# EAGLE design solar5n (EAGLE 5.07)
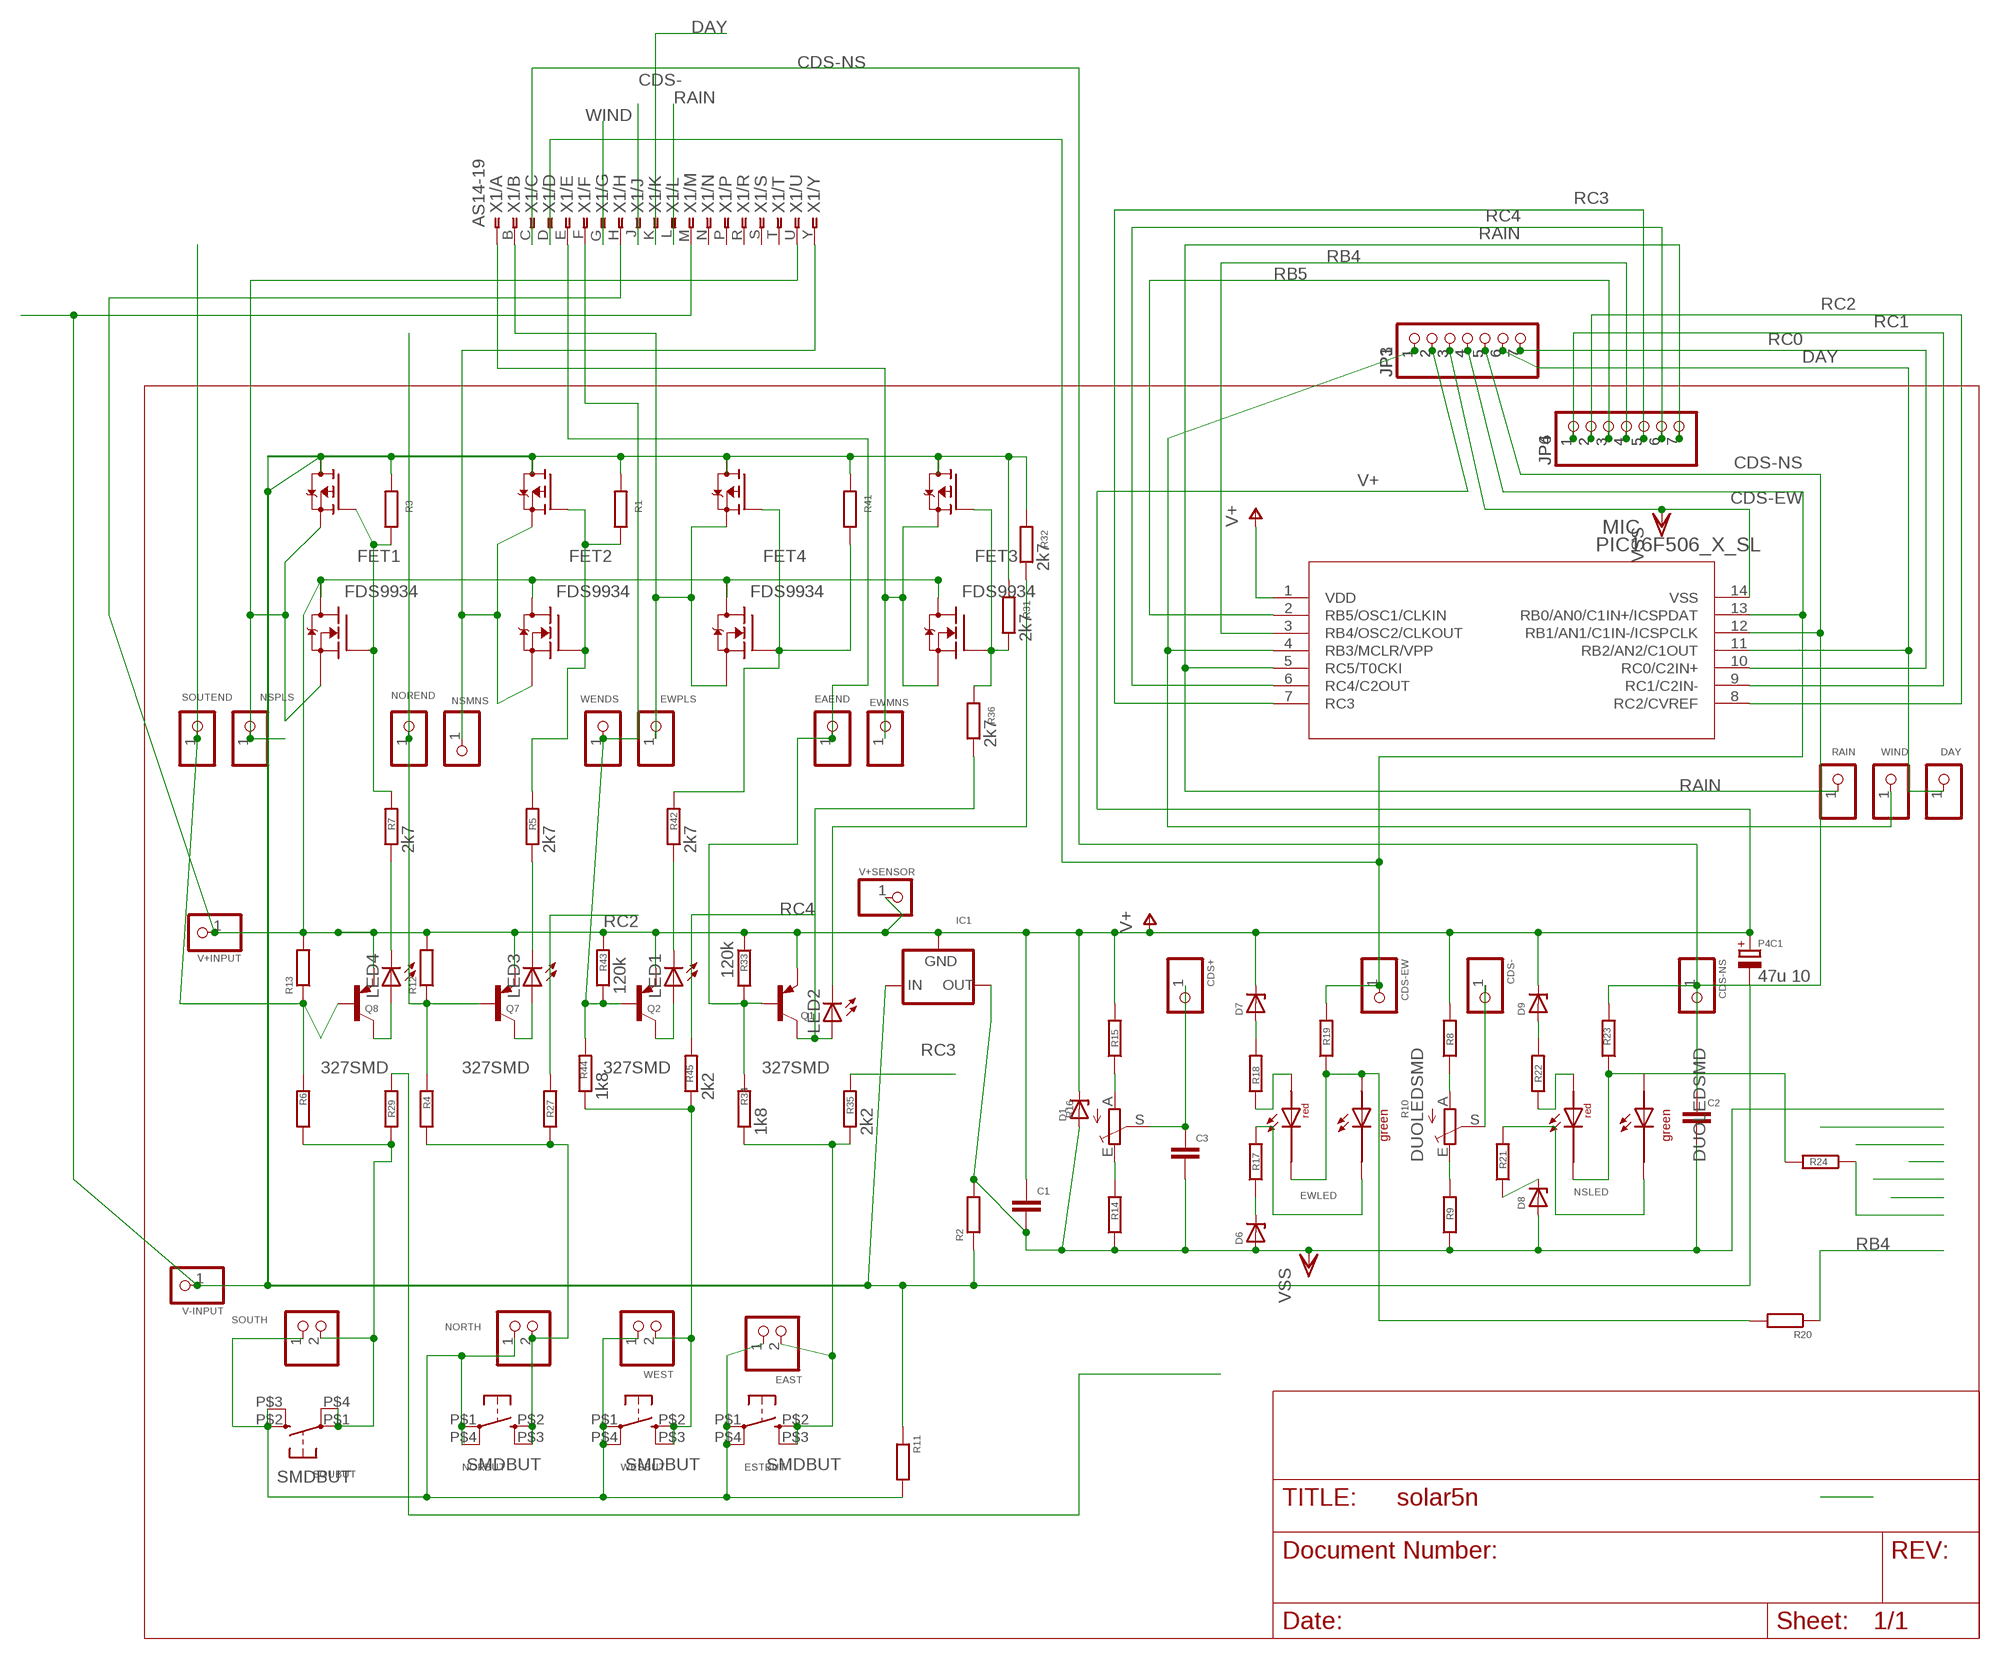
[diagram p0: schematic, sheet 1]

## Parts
C1  C-EUC1206  [C1206]
C2  C-EUC1206  [C1206]
C3  C-EUC1206  [C1206]
CDS+  PINHD-1X1INCH  [1X01]
CDS-  PINHD-1X1INCH  [1X01]
CDS-EW  PINHD-1X1INCH  [1X01]
CDS-NS  PINHD-1X1INCH  [1X01]
D1  ZENER-DIODESOD80C  [SOD80C]
D6  ZENER-DIODESOD80C  [SOD80C]
D7  ZENER-DIODESOD80C  [SOD80C]
D8  ZENER-DIODESOD80C  [SOD80C]
D9  ZENER-DIODESOD80C  [SOD80C]
DAY  PINHD-1X1INCH  [1X01]
EAEND  PINHD-1X1INCH  [1X01]
EAST  PINHD-1X2STR  [1X02]
ESTBUT  SMDBUT  [SMD10/5]
EWLED  DUOLEDSMD  [DUOLEDSMD]
EWMNS  PINHD-1X10MM6  [1X01M]
EWPLS  PINHD-1X10MM6  [1X01M]
FET1  FDS9934  [SO-8]
FET2  FDS9934  [SO-8]
FET3  FDS9934  [SO-8]
FET4  FDS9934  [SO-8]
IC1  79LXX  [79LXX]
JP1  PINHD-1X7  [1X07]
JP3  PINHD-1X7  [1X07]
JP4  PINHD-1X7  [1X07]
JP6  PINHD-1X7  [1X07]
LED1  LEDCHIPLED_1206  [CHIPLED_1206]
LED2  LEDCHIPLED_1206  [CHIPLED_1206]
LED3  LEDCHIPLED_1206  [CHIPLED_1206]
LED4  LEDCHIPLED_1206  [CHIPLED_1206]
MIC  PIC16F506_X_SL  [SOIC14_N_MC]
NORBUT  SMDBUT  [SMD10/5]
NOREND  PINHD-1X1INCH  [1X01]
NORTH  PINHD-1X2STR  [1X02]
NSLED  DUOLEDSMD  [DUOLEDSMD]
NSMNS  PINHD-1X1INCH  [1X01]
NSPLS  PINHD-1X10MM6  [1X01M]
P4C1  47u 10  CPOL-EUE5-8.5  [E5-8,5]
Q1  327SMD  BC327SMD  [SOT23-BEC]
Q2  327SMD  BC327SMD  [SOT23-BEC]
Q7  327SMD  BC327SMD  [SOT23-BEC]
Q8  327SMD  BC327SMD  [SOT23-BEC]
R1  R-EU_R0805  [R0805]
R2  R-EU_R0805  [R0805]
R3  R-EU_R0805  [R0805]
R4  R-EU_R1206  [R1206]
R5  2k7  R-EU_R0805  [R0805]
R6  R-EU_R1206  [R1206]
R7  2k7  R-EU_R0805  [R0805]
R8  R-EU_R1206  [R1206]
R9  R-EU_R0805  [R0805]
R10  TRIM_EU-CA6V  [CA6V]
R11  R-EU_R0805  [R0805]
R12  R-EU_R1206  [R1206]
R13  R-EU_R0805  [R0805]
R14  R-EU_R1206  [R1206]
R15  R-EU_R1206  [R1206]
R16  TRIM_EU-CA6V  [CA6V]
R17  R-EU_R1206  [R1206]
R18  R-EU_R1206  [R1206]
R19  R-EU_R0805  [R0805]
R20  R-EU_R0805  [R0805]
R21  R-EU_R1206  [R1206]
R22  R-EU_R1206  [R1206]
R23  R-EU_R0805  [R0805]
R24  R-EU_R0805  [R0805]
R27  R-EU_R0805  [R0805]
R29  R-EU_R0805  [R0805]
R31  2k7  R-EU_R0805  [R0805]
R32  2k7  R-EU_R0805  [R0805]
R33  120k  R-EU_R0805  [R0805]
R34  1k8  R-EU_R0805  [R0805]
R35  2k2  R-EU_R0805  [R0805]
R36  2k7  R-EU_R0805  [R0805]
R41  R-EU_R0805  [R0805]
R42  2k7  R-EU_R0805  [R0805]
R43  120k  R-EU_R0805  [R0805]
R44  1k8  R-EU_R0805  [R0805]
R45  2k2  R-EU_R0805  [R0805]
RAIN  PINHD-1X1INCH  [1X01]
SOUBUT  SMDBUT  [SMD10/5]
SOUTEND  PINHD-1X1INCH  [1X01]
SOUTH  PINHD-1X2STR  [1X02]
V+INPUT  PINHD-1X1INCH  [1X01]
V+SENSOR  PINHD-1X10MM6  [1X01M]
V-INPUT  PINHD-1X10MM6  [1X01M]
WENDS  PINHD-1X1INCH  [1X01]
WESBUT  SMDBUT  [SMD10/5]
WEST  PINHD-1X2STR  [1X02]
WIND  PINHD-1X1INCH  [1X01]
X1  AS14-19  AS14-19OLIVE  [Y28M-19TK]

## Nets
CDS-: CDS-.1 R10.S X1.J
CDS-EW: CDS-EW.1 JP1.4 JP3.4 MIC.13(RB0/AN0/C1IN+/ICSPDAT) R19.2 X1.D
CDS-NS: C2.1 CDS-NS.1 JP1.5 JP3.5 MIC.12(RB1/AN1/C1IN-/ICSPCLK) R23.2 X1.C
DAY: DAY.1 JP1.6 JP3.6 MIC.11(RB2/AN2/C1OUT) X1.K
MOTO1: EWPLS.1 FET4.1(Q1S) FET4.3(Q2S) X1.B
MOTOR1: FET1.1(Q1S) FET1.3(Q2S) NSPLS.1 X1.U
MOTOR2: FET2.1(Q1S) FET2.3(Q2S) NSMNS.1 X1.Y
MOTOR3: EWMNS.1 FET3.1(Q1S) FET3.3(Q2S) X1.A
N$1: R9.2 R10.E
N$2: LED4.A Q8.C
N$3: LED3.A Q7.C
N$4: FET2.2(Q1G) FET2.4(Q2G) R1.1 R5.2
N$5: LED4.C R7.1
N$6: EWLED.AGRN EWLED.CRED R19.1 R20.2
N$8: LED3.C R5.1
N$9: R6.1 R29.1 SOUBUT.P$1(P) SOUBUT.P$4(P1) SOUTH.2
N$10: LED1.A Q2.C
N$11: EAST.2 ESTBUT.P$2(S) ESTBUT.P$3(S1) R34.1 R35.1
N$13: R24.1
N$14: D7.A R18.2
N$17: NORBUT.P$2(S) NORBUT.P$3(S1) NORTH.2 R4.1 R27.1
N$18: R8.1 R10.A
N$19: Q8.B R6.2 R13.1 SOUTEND.1
N$20: NOREND.1 Q7.B R4.2 R12.1
N$21: R14.2 R16.E
N$22: R15.1 R16.A
N$23: C3.1 CDS+.1 R16.S
N$25: EWLED.ARED R18.1
N$27: D6.C R17.1
N$28: EWLED.CGRN R17.2
N$29: EAST.1 ESTBUT.P$1(P) ESTBUT.P$4(P1) NORBUT.P$1(P) NORBUT.P$4(P1) NORTH.1 R11.2 SOUBUT.P$2(S) SOUBUT.P$3(S1) SOUTH.1 WESBUT.P$1(P) WESBUT.P$4(P1) WEST.1
N$30: NSLED.AGRN NSLED.CRED R23.1 R24.2
N$32: Q2.B R43.1 R44.2 WENDS.1 X1.F
N$33: EAEND.1 Q1.B R33.2 R34.2 X1.E
N$37: LED2.A Q1.C R36.1
N$39: R44.1 R45.1 WESBUT.P$2(S) WESBUT.P$3(S1) WEST.2
N$41: D9.A R22.2
N$42: NSLED.ARED R22.1
N$43: D8.C R21.1
N$44: NSLED.CGRN R21.2
N$50: FET1.2(Q1G) FET1.4(Q2G) R3.1 R7.2
N$51: LED1.C R42.1
N$54: FET4.2(Q1G) FET4.4(Q2G) R41.1 R42.2
N$55: FET3.2(Q1G) FET3.4(Q2G) R31.1 R36.2
N$56: LED2.C R32.1
RAIN: JP4.7 JP6.7 MIC.5(RC5/T0CKI) RAIN.1 X1.L
RB4: JP4.4 JP6.4 MIC.3(RB4/OSC2/CLKOUT) R20.1
RB5: JP4.3 JP6.3 MIC.2(RB5/OSC1/CLKIN)
RC0: JP1.7 JP3.7 MIC.10(RC0/C2IN+)
RC1: JP4.1 JP6.1 MIC.9(RC1/C2IN-) R29.2
RC2: JP4.2 JP6.2 MIC.8(RC2/CVREF) R27.2
RC3: JP4.5 JP6.5 MIC.7(RC3) R35.2
RC4: JP4.6 JP6.6 MIC.6(RC4/C2OUT) R45.2
V+: C1.1 D1.C D7.C D9.C FET1.7(Q1D2) FET1.8(Q1D1) FET2.7(Q1D2) FET2.8(Q1D1) FET3.7(Q1D2) FET3.8(Q1D1) FET4.7(Q1D2) FET4.8(Q1D1) IC1.GND JP1.2 JP3.2 MIC.1(VDD) P4C1.+ Q1.E Q2.E Q7.E Q8.E R8.2 R12.2 R13.2 R15.2 R33.1 R43.2 V+INPUT.1 V+SENSOR.1 X1.H
V-: FET1.5(Q2D2) FET1.6(Q2D) FET2.5(Q2D2) FET2.6(Q2D) FET3.5(Q2D2) FET3.6(Q2D) FET4.5(Q2D2) FET4.6(Q2D) IC1.IN P4C1.- R1.2 R2.1 R3.2 R11.1 R31.2 R32.2 R41.2 V-INPUT.1 X1.M
VSS: C1.2 C2.2 C3.2 D1.A D6.A D8.A IC1.OUT JP1.3 JP3.3 MIC.14(VSS) R2.2 R9.1 R14.1
WIND: JP1.1 JP3.1 MIC.4(RB3/MCLR/VPP) WIND.1 X1.G
Unconnected: X1.N X1.P X1.R X1.S X1.T

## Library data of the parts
C1-C3 = rcl-2:C-EU: CAPACITOR, European symbol
CDS+ CDS- CDS-EW CDS-NS DAY EAEND EWMNS EWPLS NOREND NSMNS NSPLS RAIN SOUTEND V+INPUT V+SENSOR V-INPUT WENDS WIND = pinhead(2):PINHD-1X1: PIN HEADER
D1 D6-D9 = diode-1:ZENER-DIODE: Z-Diode
EAST NORTH SOUTH WEST = pinhead:PINHD-1X2: PIN HEADER
ESTBUT NORBUT SOUBUT WESBUT = switch-omron:SMDBUT
EWLED NSLED = led:DUOLEDSMD
FET1-FET4 = transistor-fet:FDS9934
IC1 = v-reg:79LXX: VOLTAGE REGULATOR
JP1 JP3 JP4 JP6 = pinhead:PINHD-1X7: PIN HEADER
LED1-LED4 = led:LED: LED
MIC = pic16f506mc:PIC16F506_X_SL
P4C1 = rcl:CPOL-EU: POLARIZED CAPACITOR, European symbol
Q1 Q2 Q7 Q8 = transistor-pnp:BC327*: PNP Transistror
R1-R9 R11-R15 R17-R24 R27 R29 R31-R36 R41-R45 = rcl-2:R-EU_: RESISTOR, European symbol
R10 R16 = pot:TRIM_EU-: POTENTIOMETER
X1 = con-deutsch:AS14-19: DEUTSCH Connector

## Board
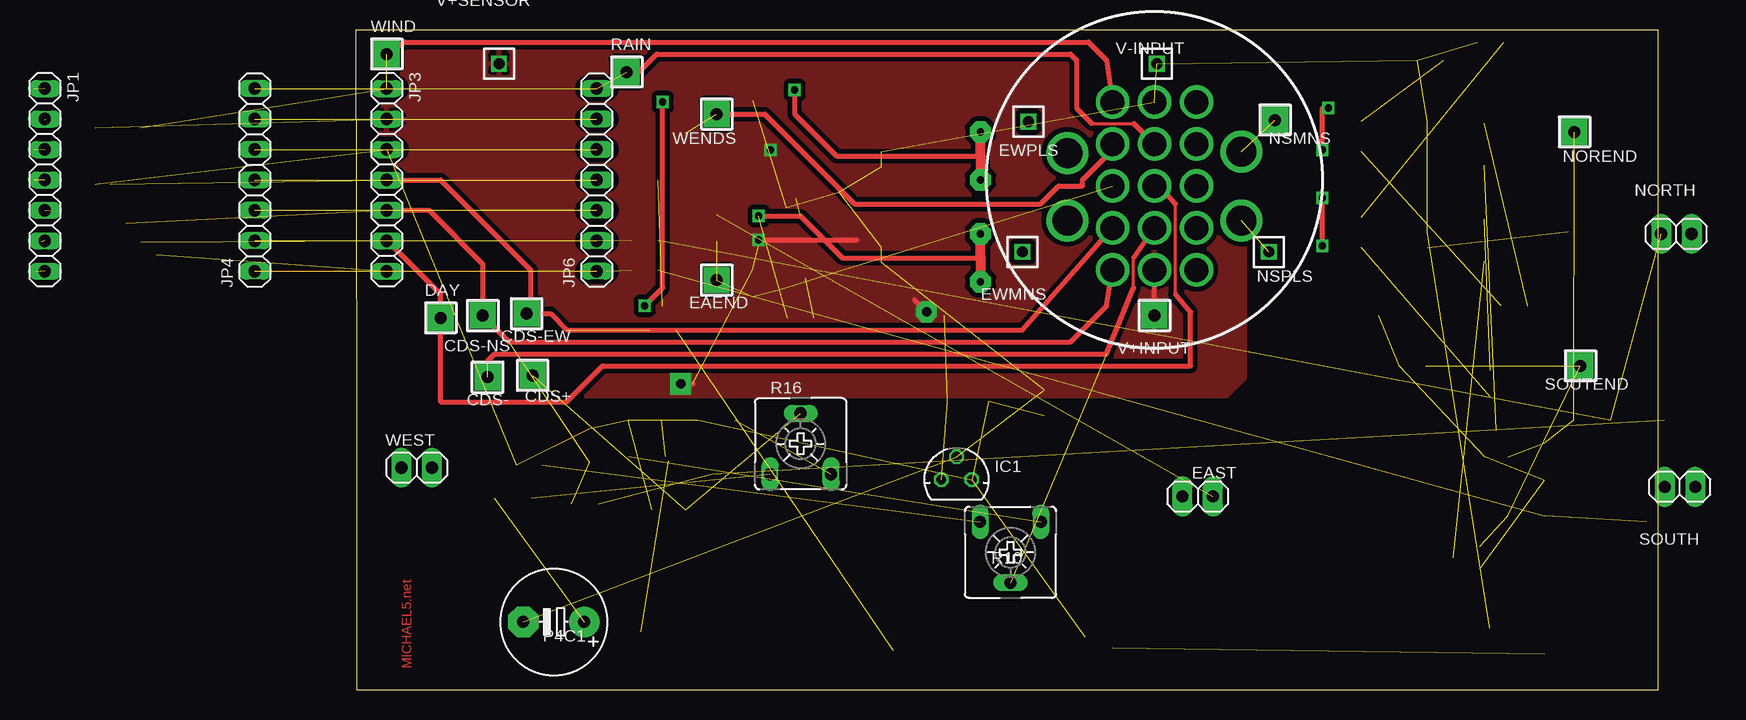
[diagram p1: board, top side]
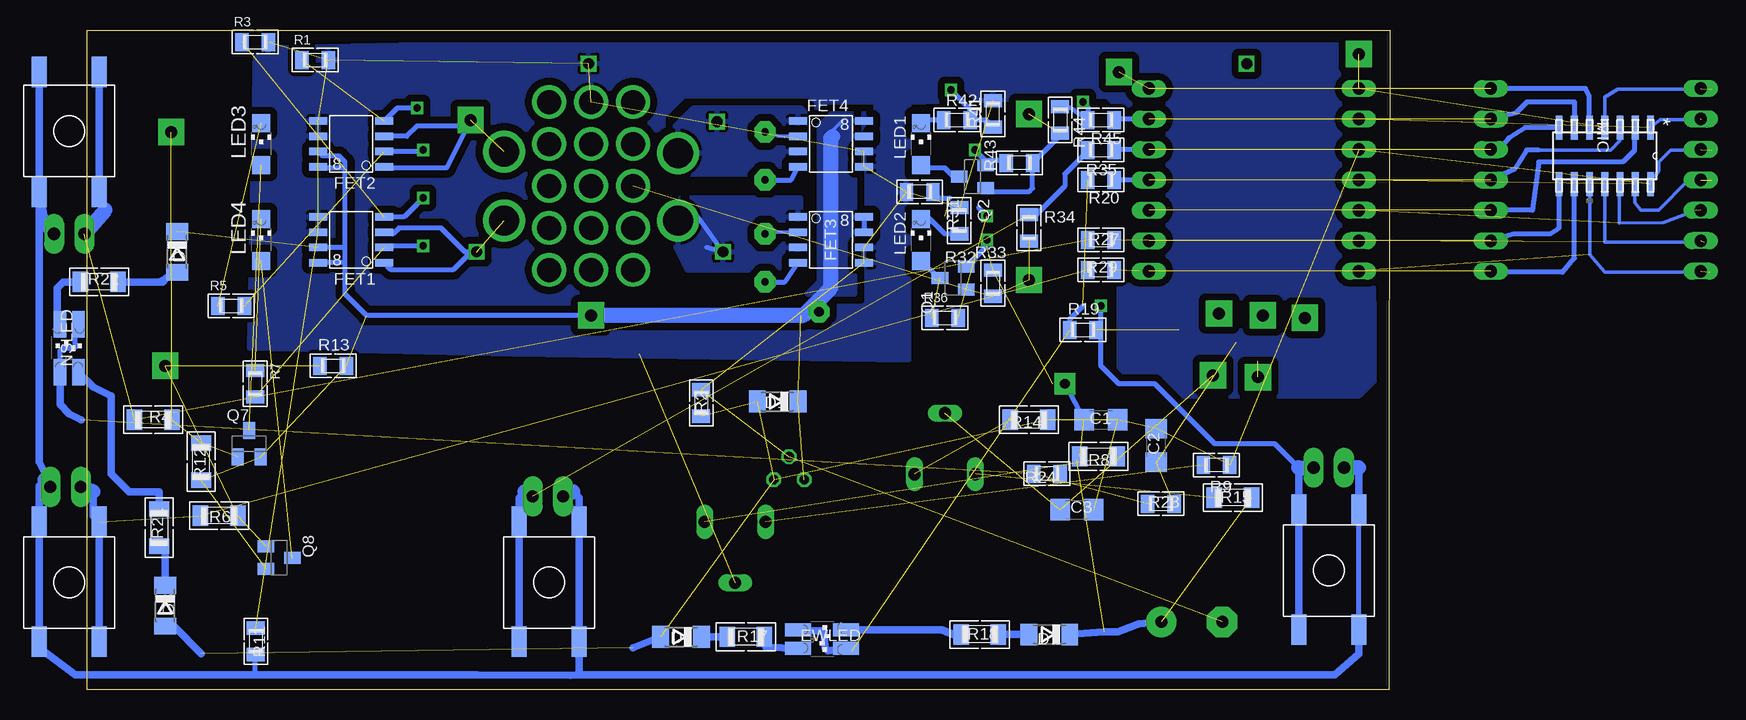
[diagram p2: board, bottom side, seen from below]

Size 108.57 x 55 mm. Coordinates in mm from the lower left corner, seen from the top.
Outline: 0.07,0 108.57,0 108.57,55 0,55 0.07,25 0.07,0
Copper layers (1*16): Top 0.035mm / dielectric 1.5mm / Bottom 0.035mm
Design rules "default *": minimum track width 40mil, minimum drill 30mil, track to track 8mil, track to pad 8mil, pad to pad 8mil, via to via 8mil, smd to smd 8mil, copper to edge 40mil, drill to drill 8mil, minimum pad ring 8mil, minimum via ring 8mil, stop-mask expansion 4mil, vias tented up to drill 0mil, thermal gap 10mil

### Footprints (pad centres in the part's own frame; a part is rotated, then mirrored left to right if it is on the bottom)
C1206 = smd 1.6 x 1.8: 1 -1.4,0; 2 1.4,0
1X01 = drill 1 pad 2.184 square: 1 0,0
SOD80C = smd 1.4 x 1.8: A 1.7,0; C -1.7,0
1X02 = drill 1.016 pad 1.676 long: 1 -1.27,0; 2 1.27,0
SMD10/5 = smd 1.27 x 2.54: P$1 -2.5,0; P$2 2.5,0; P$3 2.5,10; P$4 -2.5,10
DUOLEDSMD = smd 1.067 x 2.184: AGRN 0.77,1.95; ARED -0.77,1.95; CGRN 0.77,-2.05; CRED -0.77,-2.05
1X01M = drill 0.914 square: 1 0,0
SO-8 = smd 1.524 x 0.61: 1 -2.743,1.905; 2 -2.743,0.635; 3 -2.743,-0.635; 4 -2.743,-1.905; 5 2.743,-1.905; 6 2.743,-0.635; 7 2.743,0.635; 8 2.743,1.905
79LXX = drill 0.813 octagon: GND -1.27,0; IN 0,1.905; OUT 1.27,0
1X07 = drill 1.016 long: 1 -7.62,0; 2 -5.08,0; 3 -2.54,0; 4 0,0; 5 2.54,0; 6 5.08,0; 7 7.62,0
CHIPLED_1206 = smd 1.5 x 1.5: A 0,-1.75; C 0,1.75
SOIC14_N_MC = smd 1.981 x 0.559: 1 -2.362,3.81; 2 -2.362,2.54; 3 -2.362,1.27; 4 -2.362,0; 5 -2.362,-1.27; 6 -2.362,-2.54; 7 -2.362,-3.81; 8 2.362,-3.81; 9 2.362,-2.54; 10 2.362,-1.27; 11 2.362,0; 12 2.362,1.27; 13 2.362,2.54; 14 2.362,3.81
E5-8,5 = drill 1 pad 2.54 round: + -2.54,0 | drill 1 pad 2.54 octagon: - 2.54,0
SOT23-BEC = smd 1 x 1.4: B -0.95,-1.1; C 0,1.1; E 0.95,-1.1
R0805 = smd 1.1 x 1.5: 1 -1.1,0; 2 1.1,0
R1206 = smd 1.3 x 1.7: 1 -1.55,0; 2 1.55,0
CA6V = drill 1.016 long: A -2.54,-2.54; E 2.54,-2.54; S 0,2.54
Y28M-19TK = drill 2.5 pad 3.5 round: A -7.25,-2.875; B -7.25,2.75; U 7.25,-2.875; Y 7.25,2.875 | drill 2 pad 2.54 round: C -3.5,-7; D -3.5,-3.5; E -3.5,0; F -3.5,3.5; G -3.5,7; H 0,-7; J 0,-3.5; K 0,0; L 0,3.5; M 0,7; N 3.5,-7; P 3.5,-3.5; R 3.5,0; S 3.5,3.5; T 3.5,7

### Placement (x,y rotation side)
C1  24.07,22.5 0 bottom
C2  19.46,20.35 90 bottom
C3  26.07,15 0 bottom
CDS+  14.72,26.2 0 top
CDS-  10.97,26.05 90 top
CDS-EW  14.22,31.35 0 top
CDS-NS  10.57,31.2 90 top
D1  51.02,24.02 180 bottom
D6  59.07,4.4 180 bottom
D7  28.37,4.6 180 bottom
D8  102.07,7 270 bottom
D9  101.07,36.5 270 bottom
DAY  7.07,31 0 top
EAEND  30.07,34.15 90 top
EAST  70.17,16.1 0 top
ESTBUT  70.07,14 180 bottom
EWLED  47.27,4.2 270 bottom
EWMNS  55.57,36.5 90 top
EWPLS  56.07,47.35 90 top
FET1  86.57,37.5 180 bottom
FET2  86.57,45.5 180 bottom
FET3  46.57,37.5 0 bottom
FET4  46.57,45.5 0 bottom
IC1  50.07,17.5 0 top
JP1  not placed on the board
JP3  2.57,42.5 270 top
JP4  -8.43,42.5 90 top  (outside the outline)
JP6  20.07,42.5 90 top
LED1  39.07,45.5 0 bottom
LED2  39.07,37.5 0 bottom
LED3  94.07,45.5 0 bottom
LED4  94.07,37.5 0 bottom
MIC  -17.93,44.5 270 bottom  (outside the outline)
NORBUT  110.07,41.5 0 bottom
NOREND  101.57,46.5 0 top
NORTH  110.07,38 180 top
NSLED  110.07,28.5 0 bottom
NSMNS  76.62,47.5 0 top
NSPLS  76.12,36.5 0 top
P4C1  16.49,5.64 180 top
Q1  36.4,34.31 90 bottom
Q2  34.78,42.77 90 bottom
Q7  95.07,20.5 0 bottom
Q8  92.57,11 270 bottom
R1  89.57,52.5 0 bottom
R2  57.39,23.89 270 bottom
R3  94.57,54 0 bottom
R4  103.07,22.5 0 bottom
R5  96.57,32 0 bottom
R6  97.57,14.5 0 bottom
R7  94.57,25.5 270 bottom
R8  24.28,19.44 180 bottom
R9  14.44,18.71 180 bottom
R10  54.56,11.44 180 top
R11  94.52,4.02 270 bottom
R12  99.07,19 270 bottom
R13  88.07,27 0 bottom
R14  30.07,22.5 180 bottom
R15  13.07,16 0 bottom
R16  37.07,20.5 0 top
R17  53.67,4.4 0 bottom
R18  34.17,4.6 0 bottom
R19  25.57,30 0 bottom
R20  24.07,42.5 180 bottom
R21  102.57,13.5 90 bottom
R22  107.57,34 0 bottom
R23  19.07,15.5 0 bottom
R24  28.57,18 180 bottom
R27  24.07,37.5 0 bottom
R29  24.07,35 0 bottom
R31  39.17,41.5 180 bottom
R32  35.87,39.1 90 bottom
R33  33.07,33.89 270 bottom
R34  30.07,38.5 270 bottom
R35  24.07,45 0 bottom
R36  37.07,31 0 bottom
R41  33.07,48 90 bottom
R42  36.07,47.5 0 bottom
R43  30.86,43.91 180 bottom
R44  27.47,47.5 270 bottom
R45  24.07,47.5 0 bottom
RAIN  22.57,51.5 0 top
SOUBUT  110.07,14 180 bottom
SOUTEND  102.07,27 0 top
SOUTH  110.37,16.9 180 top
V+INPUT  66.57,31.2 90 top
V+SENSOR  11.92,52.2 90 top
V-INPUT  66.77,52.2 90 top
WENDS  30.07,48 90 top
WESBUT  5.07,15 180 bottom
WEST  5.07,18.5 0 top
WIND  2.57,53 0 top
X1  66.57,42 0 top

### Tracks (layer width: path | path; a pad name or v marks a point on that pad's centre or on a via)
CDS-  (2 unrouted)
  Top 0.254: 64.82,33.5 64.82,36
  Top 0.406: 64.82,36 X1.J | 64.82,33.5 62.57,28 11.57,28 10.97,27.4
CDS-EW  (3 unrouted)
  Top 0.406: JP3.4 7.07,42.5 14.57,35 14.57,31.7 CDS-EW.1 16.22,31.35 17.57,30 55.57,30 X1.D
  Bottom 0.305: MIC.13 -20.43,40.6 -20.93,40 -22.43,40 -24.89,42.46 -26.86,42.46
CDS-NS  (4 unrouted)
  Top 0.406: X1.C 62.57,32 59.57,29 12.77,29 CDS-NS.1 10.57,35.5 6.11,39.96 JP3.5
  Bottom 0.305: MIC.12 -19.13,41.31 -19.13,38.9 -22.81,38.92 -25.46,39.92
DAY  (2 unrouted)
  Top 0.254: 68.32,33 68.32,40.5
  Top 0.406: JP3.6 2.99,37 3.07,37 7.07,33 DAY.1 7.07,24 17.57,24 20.57,27 69.57,27 69.57,31.5 68.32,33 | 68.32,40.5 67.07,42 X1.K
  Bottom 0.305: MIC.11 -17.93,37.3 -26.24,37.3
MOTO1
  Bottom 0.406: FET4.1 49.41,47.5
  pour Bottom (isolate 0.61): 49.57,44.5 48.57,48 49.07,48.5 58.07,48.5 59.57,47 59.57,45 58.57,43 50.07,43
MOTOR1  (1 unrouted)
  Bottom 0.406: FET1.3 83.69,38 83.07,38 82.57,38.5 79.07,38.5 77.07,36.5 NSPLS.1 76.57,36.5 78.07,35 83.23,35 FET1.1
MOTOR2  (1 unrouted)
  Bottom 0.406: FET2.1 83.97,43.59 84.07,43.5 78.62,43.5 NSMNS.1 77.12,47 81.07,47 81.93,46.13 FET2.3
MOTOR3
  Bottom 0.406: 56.94,36.87 EWMNS.1 57.66,39.41
  pour Bottom (isolate 0.61): 49.07,41 59.07,41 59.57,39.5 59.57,37 58.57,35 49.57,35 49.07,36.5
N$1  (1 unrouted)
N$2  (1 unrouted)
N$3  (1 unrouted)
N$4  (via drill 0.6)  (2 unrouted)
  Top 0.406: v80.57,45 80.57,48.5 v81.07,48.5
  Bottom 0.406: FET2.2 80.7,44.87 v80.57,45 | v81.07,48.5 82.73,48.5 FET2.4
N$5  (1 unrouted)
N$6  (2 unrouted)
  Bottom 0.406: R19.1 26.67,30.9 25.57,32
  Bottom 0.61: 44.8,3.23 EWLED.AGRN 46.8,3.23 47.07,3.5 47.17,4.9 48.95,4.9 EWLED.CRED
N$8  (1 unrouted)
N$9  (2 unrouted)
  Bottom 0.61: SOUBUT.P$4 SOUBUT.P$1 108.07,14.5 108.07,16.5
  Bottom 1.27: 108.07,16.5 SOUTH.2
N$10
  Bottom 0.406: Q2.C 36.34,42.77 37.07,43.5 38.82,43.5 LED1.A
N$11  (1 unrouted)
  Bottom 0.406: R35.1 25.17,44.9 27.07,43 27.07,42 29.57,39.5 29.97,39.5 R34.1
  Bottom 0.61: ESTBUT.P$3 ESTBUT.P$2 72.57,16 72.07,16.5
  Bottom 1.27: 72.07,16.5 EAST.2
N$14
  Bottom 0.61: D7.A R18.2
N$17  (2 unrouted)
  Bottom 0.61: NORBUT.P$2 NORBUT.P$3 | NORBUT.P$2 107.57,41 | 107.07,40 NORBUT.P$2
  Bottom 1.27: NORTH.2 107.07,40
N$18  (1 unrouted)
N$19  (3 unrouted)
N$20  (3 unrouted)
N$21  (1 unrouted)
N$22  (1 unrouted)
N$23  (2 unrouted)
N$25
  Bottom 0.61: R18.1 35.49,4.42 36.07,4.5 37.35,5 EWLED.ARED
N$27
  Bottom 0.61: R17.1 D6.C
N$28
  Bottom 0.61: EWLED.CGRN 51.98,3.53 R17.2
N$29
  Bottom 0.406: WESBUT.P$4 WESBUT.P$1 | R11.2 94.57,2.6 94.57,1.25
  Bottom 0.61: WESBUT.P$1 2.57,18.5 | 67.57,1.25 ESTBUT.P$4 ESTBUT.P$1 67.57,16 68.07,16.5 | 67.57,1.25 4.57,1.25 2.57,3 WESBUT.P$4 | 67.57,1.25 68.27,1.2 76.07,1.23 79.57,1.25 94.57,1.25 109.57,1.25 112.57,3.5 SOUBUT.P$3 SOUBUT.P$2 112.57,17 112.07,17.5 | SOUTH.1 112.07,18 112.57,19 NORBUT.P$1 | NORBUT.P$1 112.07,39 | NORBUT.P$1 NORBUT.P$4
  Bottom 1.27: 2.57,18.5 WEST.1 | 68.07,16.5 EAST.1 | 112.07,17.5 SOUTH.1 | 112.07,39 NORTH.1
N$30  (2 unrouted)
  Bottom 0.406: NSLED.CRED 110.84,28.23 110.57,28.5 109.57,28.5 109.57,30.18 NSLED.AGRN
  Bottom 0.61: NSLED.CRED 110.84,23.77 110.07,23 109.07,22.5
N$32  (1 unrouted)
  Top 0.406: WENDS.1 34.07,48 41.57,40.5 57.07,40.5 58.57,42 60.57,42 60.57,42.5 63.07,45 X1.F
  Bottom 0.406: R44.2 27.47,46.2 R43.1 29.76,41.81 30.07,41.5 33.35,41.5 Q2.B
N$33  (4 unrouted)
N$37  (1 unrouted)
  Bottom 0.406: Q1.C 37.63,34.31 LED2.A
N$39  (via drill 0.6)
  Top 0.406: v25.57,49 25.57,33.5 v24.07,32
  Bottom 0.406: 7.57,18.5 9.57,20.5 14.57,20.5 19.57,25.5 22.57,25.5 24.07,27 v24.07,32 | R44.1 26.57,48.5 R45.1 25.17,48.6 v25.57,49
  Bottom 0.61: WESBUT.P$3 WESBUT.P$2 7.57,18.5
  Bottom 1.27: 7.57,18.5 WEST.2
N$41
  Bottom 0.61: D9.A 101.97,34.32 | 101.97,34.32 102.57,34 | R22.2 102.29,34 101.97,34.32
N$42
  Bottom 0.61: R22.1 110.57,34 111.07,33.5 111.07,30.68 NSLED.ARED
N$43
  Bottom 0.61: D8.C 102.07,11.58 R21.1
N$44
  Bottom 0.61: R21.2 102.57,16.5 105.07,16.5 106.57,18 106.57,24.5 108.07,25.22 NSLED.CGRN
N$50  (via drill 0.6)  (2 unrouted)
  Top 0.406: v80.57,37 v80.57,41
  Bottom 0.406: FET1.4 82.16,39.41 v80.57,41 | v80.57,37 83.69,37 FET1.2
N$51
  Bottom 0.406: LED1.C 39.07,47.5 R42.1
N$54  (via drill 0.6, 0.6 pad 1.78)
  Top 0.406: v36.57,50 36.57,48 40.07,44.5 52.07,44.5
  Top 0.813: v52.07,42.5 52.07,44.5 v52.07,46.5
  Bottom 0.305: FET4.2 50.94,46.13 v52.07,46.5
  Bottom 0.406: FET4.4 49.91,42.5 v52.07,42.5 | R41.1 33.67,47.5 R42.2 34.97,48.4 v36.57,50
N$55  (via drill 0.6, 0.6 pad 1.78)  (2 unrouted)
  Top 0.406: v33.57,39.5 37.07,39.5 40.57,36 52.07,36
  Top 0.813: v52.07,34 52.07,36 v52.07,38
  Bottom 0.305: FET3.2 50.94,38.13 v52.07,38
  Bottom 0.406: FET3.4 50.41,34 v52.07,34 | v33.57,39.5 34.27,40.2 | R31.1 38.07,41 36.67,41
N$56
  Bottom 0.406: LED2.C 38.32,39.25 37.07,38 R32.1
RAIN  (2 unrouted)
  Top 0.254: 61.37,47.2 64.87,47.2
  Top 0.406: RAIN.1 23.57,51.5 25.07,53 59.57,53 60.07,52.5 60.07,48.5 61.37,47.2 | 64.87,47.2 X1.L
  Bottom 0.406: JP4.7 -16.31,50.12 -16.63,49.5 -16.63,48.09 MIC.5
RB4  (1 unrouted)
  Bottom 0.305: MIC.3 -19.2,45.77 -18.43,45 -12.43,45
  Bottom 0.406: -12.43,45 -11.43,45 -10.43,43.4 JP4.4 | JP6.4 R20.1
RB5  (1 unrouted)
  Bottom 0.406: JP4.3 -11.89,39.96 -12.43,44 -19.43,44 -20.43,45 -20.43,46.82 MIC.2
RC0  (2 unrouted)
  Bottom 0.305: MIC.10 -16.66,36.27 -17.93,34.8 -26.7,34.8
RC1  (2 unrouted)
  Bottom 0.406: MIC.9 -15.39,35.96 -14.43,34.8 -8.55,34.8 JP4.1 | JP6.1 20.9,34.88
RC2  (2 unrouted)
  Bottom 0.406: MIC.8 -14.12,38.49 -13.33,38 -10.35,38 JP4.2
RC3  (1 unrouted)
  Bottom 0.406: MIC.7 -11.29,46.86 -9.93,46 -9.47,45.5 JP4.5 | JP6.5 22.93,45.04 R35.2
RC4  (1 unrouted)
  Bottom 0.406: JP4.6 -10.51,48.08 -11.43,49 -15.43,49 -15.43,46.9 MIC.6 | JP6.6 22.89,47.58 R45.2
V+  (via drill 0.6, 0.8 pad 1.78)  (14 unrouted)
  Top 0.406: V+INPUT.1 X1.H | v27.07,25.5 28.07,25.5 | 46.57,32.5 v47.57,31.5 47.87,31.2 48.07,31.2 | v33.57,37.5 41.77,37.5
  Bottom 0.305: 45.66,47.41 46.57,46.5 46.57,46 | 46.57,39.5 46.48,39.41 | 46.57,38 46.44,38.13 | MIC.1 -22.56,47.54 -25.89,47.54 -26.43,47 -26.46,47
  Bottom 0.406: R8.2 26.07,19.07 | v47.57,31.5 47.87,31.2 49.07,31.2 | C1.1 26.97,25.4 v27.07,25.5 | FET3.8 FET3.7 | 33.68,44.11 Q2.E | 33.68,44.11 v34.57,45 | Q1.E 35.3,35.27 33.57,37 v33.57,37.5 | 33.68,44.11 32.16,44.11 R43.2 | V+INPUT.1 85.27,31.2 87.07,33 87.07,35.5 | 87.07,35.5 87.07,37 | 87.07,37 87.07,43.5 | 87.07,43.5 87.07,44 87.57,44.5 88.95,44.5 FET2.7 | FET1.7 87.2,36.87 87.07,37 | FET1.8 87.16,35.59 87.07,35.5 | FET2.8 89.47,43.59 89.57,43.5 87.07,43.5
  Bottom 0.61: D7.C 23.77,4.8 22.67,4.8 20.89,5.5 P4C1.+
  Bottom 1.27: V+INPUT.1 49.07,31.2 48.87,31.2 46.57,33.5 46.57,38 46.57,39.5 46.57,46 46.44,46.13
  pour Bottom (isolate 0.61): 43.57,48 46.57,48 47.57,47 47.57,34 48.57,33 44.57,33 44.57,46 43.57,47.5
  pour Top (isolate 0.406): 2.57,54 70.57,54 74.07,50.5 74.07,26 72.57,24.5 1.07,24.5
V-  (18 unrouted)
  pour Bottom (isolate 0.61, rank 4): 2.07,54 70.57,54 94.57,53.5 95.07,28.5 73.07,28 40.07,27.5 40.07,49 23.57,49.5 23.07,49 22.57,49 22.57,24.5 2.57,24.5 1.07,26
VSS  (12 unrouted)
  Bottom 0.305: MIC.14 -22.43,43.33 -22.43,44 -23.43,45 -26.86,45
  Bottom 0.61: D8.A 101.37,5.3 99.07,3 | D6.A 63.07,3.5
WIND  (3 unrouted)
  Top 0.406: WIND.1 4.07,54 61.07,54 62.57,52.5 X1.G
  Bottom 0.305: MIC.4 -17.93,49.4 -19.01,50.08 -26.86,50.08

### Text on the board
Top: MICHAEL5.net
